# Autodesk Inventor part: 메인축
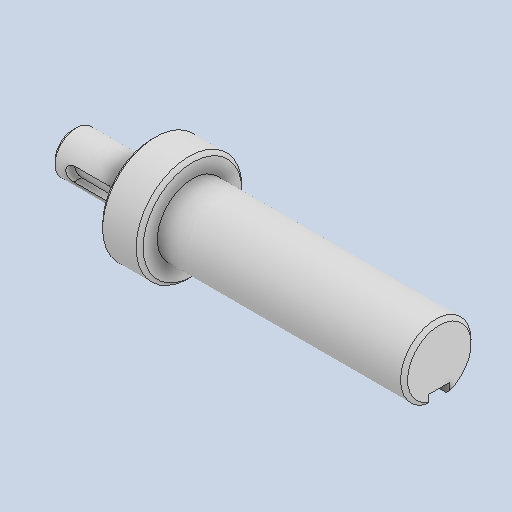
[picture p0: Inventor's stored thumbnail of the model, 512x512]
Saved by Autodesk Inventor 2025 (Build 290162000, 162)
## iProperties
Created: 2024-08
Part Number: 메인축
Material: 일반
Document SubType Name: Modeling
Designer: rese9
Density: 1 g/cm^3
Appearance: 기본값
Author: jhkim
Sending System: Autodesk Inventor 2025
Preprocessor: ST-DEVELOPER v20
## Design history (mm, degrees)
feature "솔리드1"
node "솔리드2"
